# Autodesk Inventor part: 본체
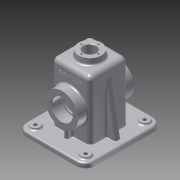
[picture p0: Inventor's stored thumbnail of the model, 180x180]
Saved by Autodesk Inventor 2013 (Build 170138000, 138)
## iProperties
Created: 2016-01
Part Number: 본체
Material: 알루미늄 6061
Document SubType Name: Modeling
Designer: User
Density: 2.71 g/cm^3
Mass: 803.199 g
Surface Area: 909.284 cm^2
Volume: 296.383 cm^3
Author: User
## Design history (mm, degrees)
sketch "스케치1"
  geometry: L1 (-65, 57.5)-(65, 57.5); L2 (65, 57.5)-(65, -57.5); L3 (65, -57.5)-(-65, -57.5); L4 (-65, -57.5)-(-65, 57.5); L5 (-65, 57.5)-(65, -57.5); L6 (65, 57.5)-(-65, -57.5); 1 further point
  constraints: 12 end point, 2 midpoint, 2 parallel, 1 horizontal, 1 perpendicular
  dimensions: "d0" = 130 distance of L1.start L1.end; "d3" = 115 distance of L1.end L2.end
extrude "돌출1" new body sketch "스케치1" distance "d4" = 8; taper "d5" = 0 deg
sketch "스케치2"
  geometry: L1 (-60, 52.5)-(60, 52.5); L2 (60, 52.5)-(60, -52.5); L3 (60, -52.5)-(-60, -52.5); L4 (-60, -52.5)-(-60, 52.5); L5 (-60, 52.5)-(60, -52.5); L6 (60, 52.5)-(-60, -52.5); 1 further point
  constraints: 12 end point, 2 midpoint, 2 parallel, 1 horizontal, 1 perpendicular
  dimensions: "d6" = 120 distance of L1.start L1.end; "d8" = 105 distance of L1.end L2.end
extrude "돌출2" join sketch "스케치2" distance "d10" = 2; taper "d11" = 0 deg
sketch "스케치3"
  geometry: L1 (-32.5, 32.5)-(32.5, 32.5); L2 (32.5, 32.5)-(32.5, -32.5); L3 (32.5, -32.5)-(-32.5, -32.5); L4 (-32.5, -32.5)-(-32.5, 32.5); L5 (-32.5, 32.5)-(32.5, -32.5); L6 (32.5, 32.5)-(-32.5, -32.5); 1 further point
  constraints: 12 end point, 2 midpoint, 2 parallel, 1 horizontal, 1 perpendicular
  dimensions: "d12" = 65 distance of L1.start L1.end; "d14" = 65 distance of L1.end L2.end
extrude "돌출3" join sketch "스케치3" distance "d15" = 100; taper "d16" = 0 deg
sketch "스케치4"
  geometry: C1 r 20 at (0, 0); C2 r 10.5 at (0, 0); 1 further point
  constraints: 2 centre point, 2 coincident
  dimensions: "d17" = 40 diameter of C1; "d19" = 21 diameter of C2
extrude "돌출4" join sketch "스케치4" distance "d20" = 10; taper "d21" = 0 deg
sketch "스케치5"
  geometry: L1 (-27.5, 27.5)-(27.5, 27.5); L2 (27.5, 27.5)-(27.5, -27.5); L3 (27.5, -27.5)-(-27.5, -27.5); L4 (-27.5, -27.5)-(-27.5, 27.5); L5 (-27.5, 27.5)-(27.5, -27.5); L6 (27.5, 27.5)-(-27.5, -27.5); 1 further point
  constraints: 12 end point, 2 midpoint, 2 parallel, 1 horizontal, 1 perpendicular
  dimensions: "d22" = 55 distance of L1.start L1.end; "d24" = 55 distance of L1.end L2.end
extrude "돌출5" cut sketch "스케치5" distance "d25" = 105; taper "d26" = 0 deg
extrude "돌출6" cut sketch "스케치4" distance "d27" = 105; taper "d28" = 0 deg
sketch "스케치6"
  geometry: L1 (0, 0)-(-100, 0) reference; L2 (10, 85)-(10, -20) reference; C1 r 27.5 at (-45, 32.5); C2 r 17.5 at (-45, 32.5); 1 further point
  constraints: 2 centre point, 1 coincident
  dimensions: "d29" = 55 diameter of C1; "d30" = 35 diameter of C2; "d31" = 55 distance from line of C2.centre L2; "d32" = 32.5 distance from line of C1.centre L1
extrude "돌출7" join sketch "스케치6" distance "d33" = 15; taper "d34" = 0 deg
extrude "돌출8" cut sketch "스케치6" distance "d35" = 2; taper "d36" = 0 deg
sketch "스케치7"
  geometry: L1 (0, 0)-(100, 0) reference; L2 (-10, -20)-(-10, 85) reference; C1 r 27.5 at (45, 32.5); C2 r 17.5 at (45, 32.5); 1 further point
  constraints: 2 centre point, 1 coincident
  dimensions: "d37" = 55 diameter of C1; "d38" = 35 diameter of C2; "d39" = 55 distance from line of L2 C2.centre; "d40" = 32.5 distance from line of L1 C1.centre
extrude "돌출9" join sketch "스케치7" distance "d41" = 15; taper "d42" = 0 deg
extrude "돌출10" cut sketch "스케치7" distance "d43" = 2; taper "d44" = 0 deg
hole "구멍1" diameter "d47" = 30; stored, may be unused: countersink angle "d51" = 90 deg, drill point angle "d53" = 118 deg; dims "d45" = 10, "d46" = 10, "d48" = 6, "d49" = 4, "d50" = 2, "d52" = 8
sketch "스케치8"
  geometry: L1 (65, 57.5)-(-65, 57.5) reference; L2 (-65, 57.5)-(-65, -57.5) reference; L3 (-65, -57.5)-(65, -57.5) reference; L4 (65, -57.5)-(65, 57.5) reference; C1 r 7.5 at (-50, 42.5); C2 r 7.5 at (50, 42.5); C3 r 7.5 at (50, -42.5); C4 r 7.5 at (-50, -42.5); 1 further point
  constraints: 4 centre point
  dimensions: "d54" = 15 diameter of C1; "d55" = 15 diameter of C2; "d56" = 15 diameter of C3; "d57" = 15 diameter of C4; "d58" = 15 distance from line of L2 C1.centre; "d59" = 100 distance of C2.centre C1.centre; "d60" = 15 distance from line of L1 C2.centre; "d61" = 15 distance from line of C1.centre L1; "d62" = 15 distance from line of L2 C4.centre; "d63" = 15 distance from line of L3 C4.centre; "d64" = 15 distance from line of L4 C3.centre; "d65" = 15 distance from line of L3 C3.centre
extrude "돌출11" join sketch "스케치8" distance "d66" = 3; taper "d67" = 0 deg
hole "구멍2" diameter "d70" = 6; stored, may be unused: countersink angle "d74" = 90 deg, drill point angle "d76" = 118 deg; dims "d68" = 10, "d69" = 10, "d71" = 6, "d72" = 4, "d73" = 2, "d75" = 8
hole "구멍3" diameter "d79" = 6; stored, may be unused: countersink angle "d83" = 90 deg, drill point angle "d85" = 118 deg; dims "d77" = 10, "d78" = 10, "d80" = 6, "d81" = 4, "d82" = 2, "d84" = 8
hole "구멍4" diameter "d88" = 6; stored, may be unused: countersink angle "d92" = 90 deg, drill point angle "d94" = 118 deg; dims "d86" = 10, "d87" = 10, "d89" = 6, "d90" = 4, "d91" = 2, "d93" = 8
hole "구멍5" diameter "d97" = 6; stored, may be unused: countersink angle "d101" = 90 deg, drill point angle "d103" = 118 deg; dims "d95" = 10, "d96" = 10, "d98" = 6, "d99" = 4, "d100" = 2, "d102" = 8
node "작업 평면1"
sketch "스케치9"
  geometry: L1 (0, -17.5)-(0, -2.5) reference; L2 (0, 90)-(0, -25) reference; L3 (0, 0)-(-100, 0) reference; L4 (0, 65)-(-100, 65) reference; L5 (-85.069, 0)-(0, -15); L6 (-85.069, 65)-(0, 80); L7 (8, -25)-(0, -25) reference; L8 (8, 90)-(0, 90) reference; 1 further point
  constraints: 4 end point, 4 point on line
  dimensions: "d104" = 10 deg angle of L5 L7; "d105" = 10 deg angle of L8 L6; "d106" = 10 distance from line of L7 L5.end; "d107" = 10 distance from line of L8 L6.end
extrude "돌출12" join sketch "스케치9" stored distance "d108" = 10; taper "d109" = 0 deg
sketch "스케치11"
  geometry: L1 (10, 60)-(10, -5) reference; L2 (27.664, 30.5)-(10, 30.5); L3 (27.664, 24.5)-(10, 24.5); L4 (10, 30.5)-(10, 24.5); C1 r 15 at (55, 27.5) reference; A1 r 27.5 centre (55, 27.5) between (27.664, 30.5) and (27.664, 24.5) reference; 2 further points
  constraints: 6 end point, 3 perpendicular, 2 point on circle, 2 point on line, 1 horizontal alignment, 1 midpoint
  dimensions: "d111" = 6 distance between parallel lines of L3 L2
extrude "돌출13" join sketch "스케치11" distance "d112" = 15; taper "d113" = 0 deg
sketch "스케치12"
  geometry: L1 (-10, -5)-(-10, 60) reference; L2 (-10, 24.5)-(-27.664, 24.5); L3 (-10, 30.5)-(-27.664, 30.5); L4 (-10, 30.5)-(-10, 24.5); C1 r 15 at (-55, 27.5) reference; A1 r 27.5 centre (-55, 27.5) between (-27.664, 24.5) and (-27.664, 30.5) reference; 2 further points
  constraints: 6 end point, 2 point on circle, 2 point on line, 1 collinear, 1 horizontal alignment, 1 midpoint, 1 parallel, 1 perpendicular
  dimensions: "d114" = 6 distance between parallel lines of L3 L2
extrude "돌출14" join sketch "스케치12" distance "d116" = 15; taper "d117" = 0 deg
fillet "모깎기1" dims "d118" = 15
sketch "스케치13"
  geometry: L1 (100, 0)-(0, 0) reference; L2 (-10, 52.5)-(-10, 12.5) reference; 2 further points
  constraints: 1 other
  dimensions: "d119" = 32.5 distance from line of point (16, 32.5) L1; "d120" = 26 distance from line of point (16, 32.5) L2
feature "엠보싱1" sketch "스케치13" dims "d121" = 0.5, "d122" = 0
fillet "모깎기2" dims "d123" = 8
fillet "모깎기3" dims "d124" = 10
fillet "모깎기4" dims "d125" = 10
fillet "모깎기5" dims "d126" = 10
fillet "모깎기6" dims "d127" = 3
sketch "스케치14" dims "d128" = 42
  geometry: C1 r 17.5 at (0, 0) reference; C2 r 27.5 at (0, 0) reference; 3 further points
  constraints: 2 horizontal alignment, 1 coincident, 2 other
hole "구멍6" sketch "스케치14" at (21, 0) diameter "d129" = 3.242; stored, may be unused: countersink angle "d133" = 90 deg, drill point angle "d135" = 118 deg; dims "d130" = 8, "d131" = 4, "d132" = 2, "d134" = 10
sketch "스케치15" dims "d139" = 42
  geometry: C1 r 17.5 at (0, 0) reference; C2 r 27.5 at (0, 0) reference; 3 further points
  constraints: 2 horizontal alignment, 1 coincident, 2 other
hole "구멍7" sketch "스케치15" at (-21, 0) diameter "d140" = 3.242; stored, may be unused: countersink angle "d144" = 90 deg, drill point angle "d146" = 118 deg; dims "d141" = 8, "d142" = 4, "d143" = 2, "d145" = 10
sketch "스케치16" dims "d150" = 29
  geometry: C1 r 10.5 at (0, 0) reference; C2 r 20 at (0, 0) reference; 2 further points
  constraints: 2 vertical alignment, 1 coincident, 2 other
hole "구멍8" sketch "스케치16" at (0, 14.5) diameter "d151" = 2.459; stored, may be unused: countersink angle "d155" = 90 deg, drill point angle "d157" = 118 deg; dims "d152" = 7, "d153" = 4, "d154" = 2, "d156" = 9
fillet "모깎기7" dims "d161" = 0.3
chamfer "모따기1" distance "d162" = 1; stored, may be unused: second distance "d163" = 2, angle "d164" = 45 deg
fillet "모깎기8" dims "d165" = 3
fillet "모깎기10" dims "d167" = 8
fillet "모깎기11" dims "d168" = 3
fillet "모깎기12" dims "d169" = 3
fillet "모깎기13" dims "d170" = 3
fillet "모깎기14" dims "d171" = 3
fillet "모깎기15" dims "d172" = 3
fillet "모깎기16" dims "d173" = 3
fillet "모깎기17" dims "d174" = 1
feature "면 기울기1" dims angle "d175" = 5 deg
fillet "모깎기18" dims "d176" = 3
node "솔리드1"
pattern_circular "원형 패턴1" dims angle "d137" = 360 deg
pattern_circular "원형 패턴2" dims angle "d148" = 360 deg
pattern_circular "원형 패턴3" dims angle "d159" = 360 deg
